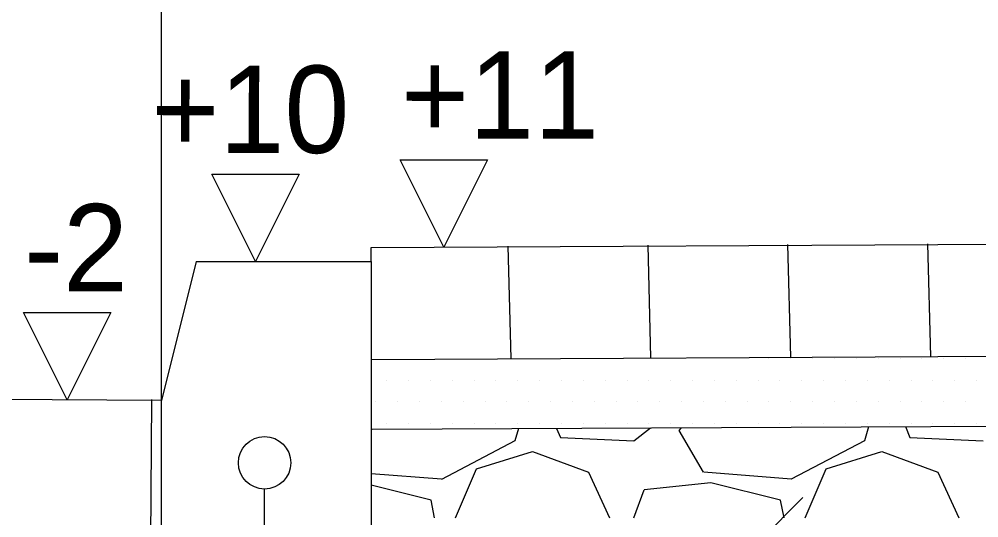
# Model space of a CAD drawing. Extents: x -219625893 to 7498339, y 5791790 to 5792761.
# Drawn here: x 7495462.42 to 7495476.15, y 5791871.52 to 5791878.65 of the extents above; entities that cross this region are included whole.
import ezdxf

# ---------------------------------------------------------------- set-up
doc = ezdxf.new("R2010")
doc.units = 0
for name, color, linetype in [('D_kons_wyp_podsypka_cem-piask', 7, 'Continuous'), ('D_kons_wyp_pospolka', 7, 'Continuous'), ('D_wymiary_500', 7, 'Continuous'), ('Level 1', 7, 'Continuous'), ('Level 10', 7, 'Continuous'), ('Level 8', 7, 'Continuous'), ('wymiary', 7, 'Continuous')]:
    doc.layers.add(name, color=color, linetype=linetype)

msp = doc.modelspace()

# ---------------------------------------------------------------- linework, layer by layer
at = {"layer": 'D_kons_wyp_podsypka_cem-piask'}
for p, q in [((7495470.65, 5791873.805), (7495470.65, 5791873.805)), ((7495470.963, 5791873.805), (7495470.963, 5791873.805)), ((7495471.275, 5791873.805), (7495471.275, 5791873.805)), ((7495471.588, 5791873.805), (7495471.588, 5791873.805)), ((7495471.9, 5791873.805), (7495471.9, 5791873.805)), ((7495472.213, 5791873.805), (7495472.213, 5791873.805)), ((7495472.525, 5791873.805), (7495472.525, 5791873.805)), ((7495472.838, 5791873.805), (7495472.838, 5791873.805)), ((7495473.15, 5791873.805), (7495473.15, 5791873.805)), ((7495473.463, 5791873.805), (7495473.463, 5791873.805)), ((7495473.775, 5791873.805), (7495473.775, 5791873.805)), ((7495474.088, 5791873.805), (7495474.088, 5791873.805)), ((7495474.4, 5791873.805), (7495474.4, 5791873.805)), ((7495474.713, 5791873.805), (7495474.713, 5791873.805)), ((7495475.025, 5791873.805), (7495475.025, 5791873.805)), ((7495475.338, 5791873.805), (7495475.338, 5791873.805)), ((7495475.65, 5791873.805), (7495475.65, 5791873.805)), ((7495475.963, 5791873.805), (7495475.963, 5791873.805)), ((7495467.682, 5791873.492), (7495467.682, 5791873.492)), ((7495467.994, 5791873.492), (7495467.994, 5791873.492)), ((7495468.307, 5791873.492), (7495468.307, 5791873.492)), ((7495468.619, 5791873.492), (7495468.619, 5791873.492)), ((7495468.932, 5791873.492), (7495468.932, 5791873.492)), ((7495469.244, 5791873.492), (7495469.244, 5791873.492)), ((7495469.557, 5791873.492), (7495469.557, 5791873.492)), ((7495469.869, 5791873.492), (7495469.869, 5791873.492)), ((7495470.182, 5791873.492), (7495470.182, 5791873.492)), ((7495470.494, 5791873.492), (7495470.494, 5791873.492)), ((7495470.807, 5791873.492), (7495470.807, 5791873.492)), ((7495471.119, 5791873.492), (7495471.119, 5791873.492)), ((7495471.432, 5791873.492), (7495471.432, 5791873.492)), ((7495471.744, 5791873.492), (7495471.744, 5791873.492)), ((7495472.057, 5791873.492), (7495472.057, 5791873.492)), ((7495472.369, 5791873.492), (7495472.369, 5791873.492)), ((7495472.682, 5791873.492), (7495472.682, 5791873.492)), ((7495472.994, 5791873.492), (7495472.994, 5791873.492)), ((7495473.307, 5791873.492), (7495473.307, 5791873.492)), ((7495473.619, 5791873.492), (7495473.619, 5791873.492)), ((7495473.932, 5791873.492), (7495473.932, 5791873.492)), ((7495474.244, 5791873.492), (7495474.244, 5791873.492)), ((7495474.557, 5791873.492), (7495474.557, 5791873.492)), ((7495474.869, 5791873.492), (7495474.869, 5791873.492)), ((7495475.182, 5791873.492), (7495475.182, 5791873.492)), ((7495475.494, 5791873.492), (7495475.494, 5791873.492)), ((7495475.807, 5791873.492), (7495475.807, 5791873.492)), ((7495476.119, 5791873.492), (7495476.119, 5791873.492)), ((7495467.525, 5791873.18), (7495467.525, 5791873.18)), ((7495467.838, 5791873.18), (7495467.838, 5791873.18)), ((7495468.15, 5791873.18), (7495468.15, 5791873.18)), ((7495468.463, 5791873.18), (7495468.463, 5791873.18)), ((7495468.775, 5791873.18), (7495468.775, 5791873.18)), ((7495469.088, 5791873.18), (7495469.088, 5791873.18)), ((7495469.4, 5791873.18), (7495469.4, 5791873.18)), ((7495469.713, 5791873.18), (7495469.713, 5791873.18)), ((7495470.025, 5791873.18), (7495470.025, 5791873.18)), ((7495470.338, 5791873.18), (7495470.338, 5791873.18)), ((7495470.65, 5791873.18), (7495470.65, 5791873.18)), ((7495470.963, 5791873.18), (7495470.963, 5791873.18)), ((7495471.275, 5791873.18), (7495471.275, 5791873.18)), ((7495471.588, 5791873.18), (7495471.588, 5791873.18)), ((7495471.9, 5791873.18), (7495471.9, 5791873.18)), ((7495472.213, 5791873.18), (7495472.213, 5791873.18)), ((7495472.525, 5791873.18), (7495472.525, 5791873.18)), ((7495472.838, 5791873.18), (7495472.838, 5791873.18)), ((7495473.15, 5791873.18), (7495473.15, 5791873.18)), ((7495473.463, 5791873.18), (7495473.463, 5791873.18)), ((7495473.775, 5791873.18), (7495473.775, 5791873.18)), ((7495474.088, 5791873.18), (7495474.088, 5791873.18)), ((7495474.4, 5791873.18), (7495474.4, 5791873.18)), ((7495474.713, 5791873.18), (7495474.713, 5791873.18)), ((7495475.025, 5791873.18), (7495475.025, 5791873.18)), ((7495475.338, 5791873.18), (7495475.338, 5791873.18)), ((7495475.65, 5791873.18), (7495475.65, 5791873.18)), ((7495475.963, 5791873.18), (7495475.963, 5791873.18)), ((7495467.682, 5791872.867), (7495467.682, 5791872.867)), ((7495467.994, 5791872.867), (7495467.994, 5791872.867)), ((7495468.307, 5791872.867), (7495468.307, 5791872.867)), ((7495468.619, 5791872.867), (7495468.619, 5791872.867)), ((7495468.932, 5791872.867), (7495468.932, 5791872.867)), ((7495469.244, 5791872.867), (7495469.244, 5791872.867)), ((7495469.557, 5791872.867), (7495469.557, 5791872.867)), ((7495469.869, 5791872.867), (7495469.869, 5791872.867)), ((7495470.182, 5791872.867), (7495470.182, 5791872.867)), ((7495470.494, 5791872.867), (7495470.494, 5791872.867)), ((7495470.807, 5791872.867), (7495470.807, 5791872.867)), ((7495471.119, 5791872.867), (7495471.119, 5791872.867)), ((7495471.432, 5791872.867), (7495471.432, 5791872.867)), ((7495471.744, 5791872.867), (7495471.744, 5791872.867)), ((7495472.057, 5791872.867), (7495472.057, 5791872.867)), ((7495472.369, 5791872.867), (7495472.369, 5791872.867)), ((7495472.682, 5791872.867), (7495472.682, 5791872.867)), ((7495472.994, 5791872.867), (7495472.994, 5791872.867)), ((7495473.307, 5791872.867), (7495473.307, 5791872.867)), ((7495473.619, 5791872.867), (7495473.619, 5791872.867)), ((7495473.932, 5791872.867), (7495473.932, 5791872.867)), ((7495474.244, 5791872.867), (7495474.244, 5791872.867)), ((7495474.557, 5791872.867), (7495474.557, 5791872.867)), ((7495474.869, 5791872.867), (7495474.869, 5791872.867)), ((7495475.182, 5791872.867), (7495475.182, 5791872.867)), ((7495475.494, 5791872.867), (7495475.494, 5791872.867)), ((7495475.807, 5791872.867), (7495475.807, 5791872.867)), ((7495476.119, 5791872.867), (7495476.119, 5791872.867))]:
    msp.add_line(p, q, dxfattribs=at)
at = {"layer": 'D_kons_wyp_pospolka'}
for p, q in [((7495469.566, 5791872.8), (7495469.515, 5791872.624)), ((7495470.111, 5791872.803), (7495470.166, 5791872.673)), ((7495471.216, 5791872.624), (7495471.456, 5791872.81)), ((7495472.215, 5791872.174), (7495471.865, 5791872.774)), ((7495471.866, 5791872.774), (7495471.9, 5791872.812)), ((7495474.573, 5791872.825), (7495474.515, 5791872.624)), ((7495475.101, 5791872.828), (7495475.166, 5791872.673)), ((7495469.516, 5791872.623), (7495468.466, 5791872.073)), ((7495470.166, 5791872.674), (7495471.216, 5791872.624)), ((7495474.516, 5791872.624), (7495473.466, 5791872.074)), ((7495475.166, 5791872.674), (7495476.216, 5791872.624)), ((7495468.966, 5791872.224), (7495469.766, 5791872.474)), ((7495469.766, 5791872.474), (7495470.566, 5791872.174)), ((7495473.966, 5791872.224), (7495474.766, 5791872.474)), ((7495474.766, 5791872.474), (7495475.566, 5791872.174)), ((7495468.666, 5791871.524), (7495468.966, 5791872.224)), ((7495473.666, 5791871.524), (7495473.966, 5791872.224)), ((7495468.466, 5791872.074), (7495467.458, 5791872.154)), ((7495470.566, 5791872.174), (7495470.866, 5791871.524)), ((7495473.466, 5791872.074), (7495472.216, 5791872.174)), ((7495475.566, 5791872.174), (7495475.866, 5791871.524)), ((7495468.316, 5791871.774), (7495467.458, 5791871.988)), ((7495472.316, 5791872.024), (7495471.366, 5791871.924)), ((7495473.316, 5791871.774), (7495472.316, 5791872.024)), ((7495471.216, 5791871.524), (7495471.366, 5791871.924)), ((7495468.366, 5791871.524), (7495468.316, 5791871.774)), ((7495473.366, 5791871.524), (7495473.316, 5791871.774))]:
    msp.add_line(p, q, dxfattribs=at)
at = {"layer": 'D_wymiary_500'}
for p, q in [((7495464.458, 5791873.199), (7495464.458, 5791895.3)), ((7495467.471, 5791872.79), (7495494.471, 5791872.925))]:
    msp.add_line(p, q, dxfattribs=at)
at = {"layer": 'Level 1'}
for p, q in [((7495468.499, 5791875.395), (7495467.875, 5791876.645)), ((7495467.875, 5791876.645), (7495469.125, 5791876.644)), ((7495469.125, 5791876.644), (7495468.499, 5791875.395)), ((7495465.804, 5791875.19), (7495465.18, 5791876.44)), ((7495465.18, 5791876.44), (7495466.43, 5791876.439)), ((7495466.43, 5791876.439), (7495465.804, 5791875.19)), ((7495463.11, 5791873.209), (7495462.486, 5791874.459)), ((7495462.486, 5791874.459), (7495463.736, 5791874.458)), ((7495463.736, 5791874.458), (7495463.11, 5791873.209))]:
    msp.add_line(p, q, dxfattribs=at)
at = {"layer": 'Level 10'}
for p, q in [((7495467.458, 5791875.39), (7495494.458, 5791875.525)), ((7495467.458, 5791875.19), (7495467.458, 5791875.39)), ((7495469.46, 5791873.8), (7495469.418, 5791875.411)), ((7495471.462, 5791873.81), (7495471.42, 5791875.421)), ((7495473.464, 5791873.82), (7495473.422, 5791875.431)), ((7495475.465, 5791873.83), (7495475.424, 5791875.441)), ((7495464.955, 5791875.19), (7495464.458, 5791873.202)), ((7495467.466, 5791873.79), (7495494.466, 5791873.925)), ((7495464.458, 5791873.202), (7495414.458, 5791873.452)), ((7495464.308, 5791871.203), (7495464.318, 5791873.214))]:
    msp.add_line(p, q, dxfattribs=at)
at = {"layer": 'Level 8'}
for p, q in [((7495464.955, 5791875.19), (7495467.458, 5791875.19)), ((7495467.458, 5791875.19), (7495467.458, 5791869.19)), ((7495464.458, 5791869.19), (7495464.458, 5791873.202))]:
    msp.add_line(p, q, dxfattribs=at)
at = {"layer": 'wymiary'}
for p, q in [((7495465.933, 5791845.429), (7495465.933, 5791871.935)), ((7495472.385, 5791870.565), (7495473.636, 5791871.814))]:
    msp.add_line(p, q, dxfattribs=at)
msp.add_circle((7495465.933, 5791872.31), 0.375, dxfattribs=at)

# ---------------------------------------------------------------- texts
for s, p in [('+11', (7495467.882, 5791876.948)), ('+10', (7495464.311, 5791876.743)), ('-2', (7495462.493, 5791874.762))]:
    msp.add_text(s, height=1.25, rotation=359.9571, dxfattribs=at).set_placement(p)

doc.saveas('drawing.dxf')
